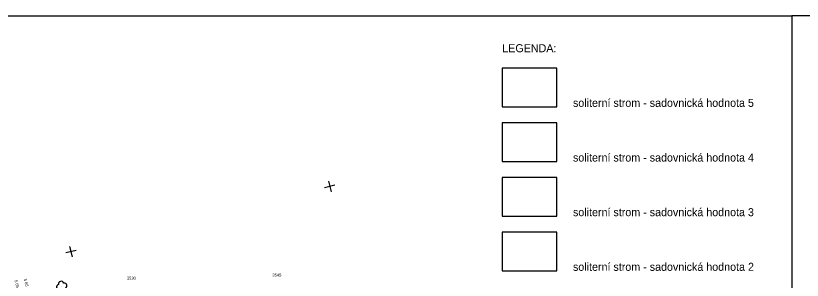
# Model space of a CAD drawing. Extents: x -740053 to -737517, y -1033516 to -1032488.
# Drawn here: x -739134.6 to -738987.3, y -1032556 to -1032506.5 of the extents above; entities that cross this region are included whole.
import ezdxf

# ---------------------------------------------------------------- set-up
doc = ezdxf.new("R2010")
doc.units = 0
for name, color, linetype in [('bod-cislo', 7, 'Continuous'), ('bod-vyska', 7, 'Continuous'), ('ctv-sit', 7, 'Continuous'), ('Predmety bez rozlišeni', 7, 'Continuous'), ('promika-formát', 7, 'Continuous'), ('Znacky-kultury', 7, 'Continuous')]:
    doc.layers.add(name, color=color, linetype=linetype)

# ---------------------------------------------------------------- blocks, each defined once
blk = doc.blocks.new('POINT_DISPLAY')
blk.add_line((0, 0), (0, 0))
blk = doc.blocks.new('p_strom')
for centre, start, end in [((-1, 0), 90, 270), ((0, 1), 0, 180), ((1, 0), 270, 90), ((0, -1), 180, 0)]:
    blk.add_arc(centre, 1, start, end)
at = {"rotation": -180}
blk.add_blockref('POINT_DISPLAY', (0, 0), dxfattribs=at)
blk = doc.blocks.new('ctvsit')
for p, q in [((2, 0), (-2, 0)), ((0, -2), (0, 2))]:
    blk.add_line(p, q)

msp = doc.modelspace()

# ---------------------------------------------------------------- linework, layer by layer
at = {"layer": 'Predmety bez rozlišeni'}
for p, q in [((-739199.25, -1032506.48), (-739094.25, -1032506.48)), ((-739094.25, -1032506.48), (-738989.25, -1032506.48))]:
    msp.add_line(p, q, dxfattribs=at)
for points in [[(-739043.46, -1032523.54), (-739033.22, -1032523.54), (-739033.22, -1032516.31), (-739043.46, -1032516.31)], [(-739043.46, -1032533.78), (-739033.22, -1032533.78), (-739033.22, -1032526.54), (-739043.46, -1032526.54)], [(-739043.46, -1032544.01), (-739033.22, -1032544.01), (-739033.22, -1032536.78), (-739043.46, -1032536.78)], [(-739043.46, -1032554.24), (-739033.22, -1032554.24), (-739033.22, -1032547.01), (-739043.46, -1032547.01)]]:
    msp.add_lwpolyline(points, close=True, dxfattribs=at)
at = {"layer": 'promika-formát'}
msp.add_lwpolyline([(-738989.25, -1032654.98), (-738884.25, -1032654.98), (-738884.25, -1032506.48), (-738989.25, -1032506.48)], close=True, dxfattribs=at)

# ---------------------------------------------------------------- block references
at = {"layer": 'ctv-sit', "xscale": 0.49999999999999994, "yscale": 0.5, "rotation": 104.13020959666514}
for p in [(-739075.76, -1032538.45), (-739124.25, -1032550.65)]:
    msp.add_blockref('ctvsit', p, dxfattribs=at)
at = {"layer": 'Znacky-kultury', "xscale": 0.49999999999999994, "yscale": 0.5, "rotation": -75.86979040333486}
msp.add_blockref('p_strom', (-739125.97, -1032557.18), dxfattribs=at)

# ---------------------------------------------------------------- texts
at = {"layer": 'bod-cislo'}
for s, p in [('3545', (-739086.52, -1032555.31)), ('3530', (-739113.78, -1032555.89))]:
    msp.add_text(s, height=0.55, dxfattribs=at).set_placement(p)
at = {"layer": 'bod-vyska'}
for p in [(-739134.82, -1032556.03), (-739133.08, -1032555.8)]:
    msp.add_text('5 65', height=0.55, rotation=284.1302, dxfattribs=at).set_placement(p)
at = {"layer": 'Predmety bez rozlišeni'}
for s, p in [('LEGENDA:', (-739043.46, -1032513.31)), ('soliterní strom - sadovnická hodnota 5', (-739030.22, -1032523.54)), ('soliterní strom - sadovnická hodnota 4', (-739030.22, -1032533.78)), ('soliterní strom - sadovnická hodnota 3', (-739030.22, -1032544.01)), ('soliterní strom - sadovnická hodnota 2 ', (-739030.22, -1032554.24))]:
    msp.add_text(s, height=1.5, rotation=360, dxfattribs=at).set_placement(p)

doc.saveas('drawing.dxf')
